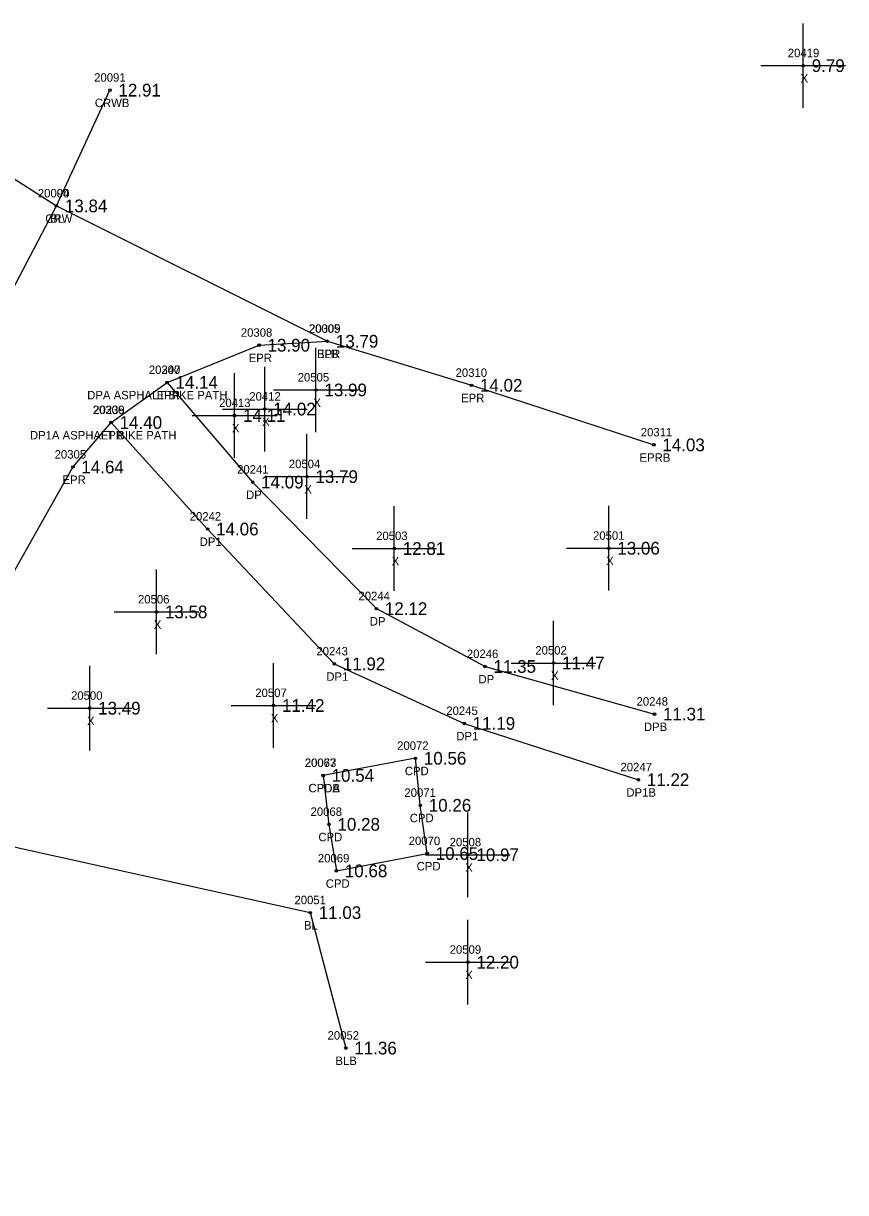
# Model space of a CAD drawing. Extents: x 2072302 to 2072980, y 127650 to 129736.
# Drawn here: x 2072882.9 to 2072980, y 128531.6 to 128669.8 of the extents above; entities that cross this region are included whole.
import ezdxf

# ---------------------------------------------------------------- set-up
doc = ezdxf.new("R2010")
doc.units = 0
for name, color, linetype in [('RD_DTM_BkLn1', 7, 'Continuous'), ('RD_DTM_BkLn_txCode', 7, 'Continuous'), ('RD_EX_Conc', 7, 'Continuous'), ('RD_EX_Conc_txCode', 7, 'Continuous'), ('RD_EX_Driveway', 7, 'Continuous'), ('RD_EX_Driveway_txCode', 7, 'Continuous'), ('RD_EX_Misc', 7, 'Continuous'), ('RD_EX_Misc_txCode', 7, 'Continuous'), ('RD_EX_Road', 7, 'Continuous'), ('RD_EX_Road_txCode', 7, 'Continuous'), ('RD_EX_TX_Conc_ELEV', 7, 'Continuous'), ('RD_EX_TX_Driveway_ELEV', 7, 'Continuous'), ('RD_EX_TX_Misc_ELEV', 7, 'Continuous'), ('RD_EX_TX_Road_ELEV', 7, 'Continuous'), ('RD_HC_Survey_ELEV', 7, 'Continuous'), ('RD_HC_Survey_txCode', 7, 'Continuous'), ('RD_SMD_Locator', 7, 'Continuous')]:
    doc.layers.add(name, color=color, linetype=linetype)

msp = doc.modelspace()

# ---------------------------------------------------------------- linework, layer by layer
at = {"layer": 'RD_DTM_BkLn1'}
for points in [[(2072853.07, 128669.78), (2072886.77, 128648.23), (2072918.79, 128632.23)], [(2072783.68, 128341.98), (2072775.38, 128381.91), (2072773.13, 128410.46), (2072778.13, 128436.13), (2072789.72, 128460.89), (2072826.62, 128532.44), (2072863.13, 128603.15), (2072886.77, 128648.23), (2072893.1, 128661.91)], [(2072791.29, 128345.62), (2072800.72, 128429.53), (2072808.9, 128452.58), (2072870.32, 128568.64), (2072876.57, 128573.6), (2072916.77, 128564.68), (2072920.97, 128548.67)]]:
    msp.add_lwpolyline(points, dxfattribs=at)
at = {"layer": 'RD_EX_Conc'}
msp.add_lwpolyline([(2072918.29, 128580.9), (2072918.98, 128575.12), (2072919.85, 128569.62), (2072930.59, 128571.67), (2072929.77, 128577.37), (2072929.19, 128582.93), (2072918.29, 128580.9)], dxfattribs=at)
at = {"layer": 'RD_EX_Driveway'}
for points in [[(2072899.84, 128627.36), (2072909.96, 128615.58), (2072924.58, 128600.62), (2072937.42, 128593.78), (2072957.44, 128588.15)], [(2072893.24, 128622.62), (2072904.64, 128610.03), (2072919.61, 128594.09), (2072934.96, 128587.05), (2072955.54, 128580.39)]]:
    msp.add_lwpolyline(points, dxfattribs=at)
at = {"layer": 'RD_EX_Misc'}
for p, q in [((2072975.02, 128659.81), (2072975.02, 128669.81)), ((2072970.02, 128664.81), (2072980.02, 128664.81)), ((2072917.44, 128621.47), (2072917.44, 128631.47)), ((2072911.39, 128619.21), (2072911.39, 128629.21)), ((2072907.82, 128618.45), (2072907.82, 128628.45)), ((2072912.44, 128626.47), (2072922.44, 128626.47)), ((2072906.39, 128624.21), (2072916.39, 128624.21)), ((2072902.82, 128623.45), (2072912.82, 128623.45)), ((2072916.38, 128611.23), (2072916.38, 128621.23)), ((2072911.38, 128616.23), (2072921.38, 128616.23)), ((2072926.7, 128602.73), (2072926.7, 128612.73)), ((2072952.05, 128602.76), (2072952.05, 128612.76)), ((2072921.7, 128607.73), (2072931.7, 128607.73)), ((2072947.05, 128607.76), (2072957.05, 128607.76)), ((2072898.59, 128595.23), (2072898.59, 128605.23)), ((2072893.59, 128600.23), (2072903.59, 128600.23)), ((2072945.52, 128589.19), (2072945.52, 128599.19)), ((2072890.7, 128583.85), (2072890.7, 128593.85)), ((2072912.43, 128584.17), (2072912.43, 128594.17)), ((2072940.52, 128594.19), (2072950.52, 128594.19)), ((2072907.43, 128589.17), (2072917.43, 128589.17)), ((2072885.7, 128588.85), (2072895.7, 128588.85)), ((2072935.4, 128566.52), (2072935.4, 128576.52)), ((2072930.4, 128571.52), (2072940.4, 128571.52)), ((2072935.4, 128553.82), (2072935.4, 128563.82)), ((2072930.4, 128558.82), (2072940.4, 128558.82))]:
    msp.add_line(p, q, dxfattribs=at)
at = {"layer": 'RD_EX_Road'}
msp.add_lwpolyline([(2072789.45, 128345.69), (2072789.46, 128382.93), (2072788.01, 128408.09), (2072794.06, 128431.26), (2072804.3, 128453.88), (2072840.7, 128525.64), (2072876.68, 128596.08), (2072888.72, 128617.36), (2072893.24, 128622.62), (2072899.84, 128627.36), (2072910.72, 128631.76), (2072918.79, 128632.23), (2072935.82, 128627.02), (2072957.37, 128619.98)], dxfattribs=at)
at = {"layer": 'RD_SMD_Locator'}
for centre in [(2072975.02, 128664.81), (2072893.1, 128661.91), (2072886.77, 128648.23), (2072886.77, 128648.23), (2072910.72, 128631.76), (2072918.79, 128632.23), (2072918.79, 128632.23), (2072899.84, 128627.36), (2072899.84, 128627.36), (2072917.44, 128626.47), (2072935.82, 128627.02), (2072907.82, 128623.45), (2072911.39, 128624.21), (2072893.24, 128622.62), (2072893.24, 128622.62), (2072957.37, 128619.98), (2072888.72, 128617.36), (2072909.96, 128615.58), (2072916.38, 128616.23), (2072904.64, 128610.03), (2072926.7, 128607.73), (2072952.05, 128607.76), (2072898.59, 128600.23), (2072924.58, 128600.62), (2072919.61, 128594.09), (2072937.42, 128593.78), (2072945.52, 128594.19), (2072912.43, 128589.17), (2072890.7, 128588.85), (2072957.44, 128588.15), (2072934.96, 128587.05), (2072929.19, 128582.93), (2072918.29, 128580.9), (2072918.29, 128580.9), (2072955.54, 128580.39), (2072929.77, 128577.37), (2072918.98, 128575.12), (2072930.59, 128571.67), (2072935.4, 128571.52), (2072919.85, 128569.62), (2072916.77, 128564.68), (2072935.4, 128558.82), (2072920.97, 128548.67)]:
    msp.add_circle(centre, 0.15, dxfattribs=at)

# ---------------------------------------------------------------- texts
at = {"layer": 'RD_DTM_BkLn_txCode'}
for s, p in [('20004', (2072884.58, 128649.23)), ('BL', (2072886.02, 128646.23)), ('20005', (2072916.59, 128633.23)), ('BLB', (2072917.56, 128630.23)), ('20051', (2072914.9, 128565.68)), ('BL', (2072916.02, 128562.68)), ('20052', (2072918.81, 128549.67)), ('BLB', (2072919.74, 128546.67))]:
    msp.add_text(s, height=1, dxfattribs=at).set_placement(p)
at = {"layer": 'RD_EX_Conc_txCode'}
for s, p in [('20072', (2072927.03, 128583.93)), ('20067', (2072916.11, 128581.9)), ('20073', (2072916.13, 128581.9)), ('CPD', (2072927.94, 128580.93)), ('CPDA', (2072916.55, 128578.9)), ('CPDB', (2072916.57, 128578.9)), ('20071', (2072927.89, 128578.37)), ('20068', (2072916.8, 128576.12)), ('CPD', (2072928.52, 128575.37)), ('CPD', (2072917.73, 128573.12)), ('20070', (2072928.4, 128572.67)), ('20069', (2072917.67, 128570.62)), ('CPD', (2072929.34, 128569.67)), ('CPD', (2072918.6, 128567.62))]:
    msp.add_text(s, height=1, dxfattribs=at).set_placement(p)
at = {"layer": 'RD_EX_Driveway_txCode'}
for s, p in [('20240', (2072897.69, 128628.36)), ('DPA ASPHALT BIKE PATH', (2072890.41, 128625.36)), ('20239', (2072891.12, 128623.62)), ('DP1A ASPHALT BIKE PATH', (2072883.64, 128620.62)), ('20241', (2072908.12, 128616.58)), ('DP', (2072909.18, 128613.58)), ('20242', (2072902.52, 128611.03)), ('DP1', (2072903.7, 128608.03)), ('20244', (2072922.46, 128601.62)), ('DP', (2072923.8, 128598.62)), ('20243', (2072917.49, 128595.09)), ('20246', (2072935.27, 128594.78)), ('DP1', (2072918.66, 128592.09)), ('DP', (2072936.64, 128591.78)), ('20245', (2072932.84, 128588.05)), ('20248', (2072955.32, 128589.15)), ('DPB', (2072956.19, 128586.15)), ('DP1', (2072934.02, 128585.05)), ('20247', (2072953.42, 128581.39)), ('DP1B', (2072954.12, 128578.39))]:
    msp.add_text(s, height=1, dxfattribs=at).set_placement(p)
at = {"layer": 'RD_EX_Misc_txCode'}
for s, p in [('20419', (2072973.19, 128665.81)), ('X', (2072974.71, 128662.81)), ('20505', (2072915.28, 128627.47)), ('20413', (2072905.99, 128624.45)), ('20412', (2072909.56, 128625.21)), ('X', (2072917.13, 128624.47)), ('X', (2072907.51, 128621.45)), ('X', (2072911.08, 128622.21)), ('20504', (2072914.23, 128617.23)), ('X', (2072916.07, 128614.23)), ('20501', (2072950.18, 128608.76)), ('20503', (2072924.55, 128608.73)), ('X', (2072926.39, 128605.73)), ('X', (2072951.74, 128605.76)), ('20506', (2072896.41, 128601.23)), ('X', (2072898.28, 128598.23)), ('20502', (2072943.36, 128595.19)), ('X', (2072945.21, 128592.19)), ('20500', (2072888.5, 128589.85)), ('20507', (2072910.27, 128590.17)), ('X', (2072890.39, 128586.85)), ('X', (2072912.11, 128587.17)), ('20508', (2072933.24, 128572.52)), ('X', (2072935.08, 128569.52)), ('20509', (2072933.24, 128559.82)), ('X', (2072935.08, 128556.82))]:
    msp.add_text(s, height=1, dxfattribs=at).set_placement(p)
at = {"layer": 'RD_EX_Road_txCode'}
for s, p in [('20308', (2072908.56, 128632.76)), ('20309', (2072916.63, 128633.23)), ('EPR', (2072909.49, 128629.76)), ('EPR', (2072917.56, 128630.23)), ('20307', (2072897.69, 128628.36)), ('20310', (2072933.94, 128628.02)), ('EPR', (2072898.61, 128625.36)), ('EPR', (2072934.59, 128625.02)), ('20306', (2072891.06, 128623.62)), ('EPR', (2072892.01, 128620.62)), ('20311', (2072955.82, 128620.98)), ('20305', (2072886.56, 128618.36)), ('EPRB', (2072955.67, 128617.98)), ('EPR', (2072887.49, 128615.36))]:
    msp.add_text(s, height=1, dxfattribs=at).set_placement(p)
at = {"layer": 'RD_EX_TX_Conc_ELEV'}
for s, p in [('10.56', (2072930.19, 128582.18)), ('10.54', (2072919.29, 128580.15)), ('10.54', (2072919.29, 128580.15)), ('10.26', (2072930.77, 128576.62)), ('10.28', (2072919.98, 128574.37)), ('10.65', (2072931.59, 128570.92)), ('10.68', (2072920.85, 128568.87))]:
    msp.add_text(s, height=1.5, dxfattribs=at).set_placement(p)
at = {"layer": 'RD_EX_TX_Driveway_ELEV'}
for s, p in [('14.14', (2072900.84, 128626.61)), ('14.40', (2072894.24, 128621.87)), ('14.09', (2072910.96, 128614.83)), ('14.06', (2072905.64, 128609.28)), ('12.12', (2072925.58, 128599.87)), ('11.92', (2072920.61, 128593.34)), ('11.35', (2072938.42, 128593.03)), ('11.19', (2072935.96, 128586.3)), ('11.31', (2072958.44, 128587.4)), ('11.22', (2072956.54, 128579.64))]:
    msp.add_text(s, height=1.5, dxfattribs=at).set_placement(p)
at = {"layer": 'RD_EX_TX_Misc_ELEV'}
for s, p in [('9.79', (2072976.02, 128664.06)), ('13.84', (2072887.77, 128647.48)), ('13.79', (2072919.79, 128631.48)), ('13.99', (2072918.44, 128625.72)), ('14.02', (2072912.39, 128623.46)), ('14.11', (2072908.82, 128622.7)), ('13.79', (2072917.38, 128615.48)), ('12.81', (2072927.7, 128606.98)), ('13.06', (2072953.05, 128607.01)), ('13.58', (2072899.59, 128599.48)), ('11.47', (2072946.52, 128593.44)), ('13.49', (2072891.7, 128588.1)), ('11.42', (2072913.43, 128588.42)), ('10.97', (2072936.4, 128570.77)), ('11.03', (2072917.77, 128563.93)), ('12.20', (2072936.4, 128558.07)), ('11.36', (2072921.97, 128547.92))]:
    msp.add_text(s, height=1.5, dxfattribs=at).set_placement(p)
at = {"layer": 'RD_EX_TX_Road_ELEV'}
for s, p in [('13.90', (2072911.72, 128631.01)), ('13.79', (2072919.79, 128631.48)), ('14.14', (2072900.84, 128626.61)), ('14.02', (2072936.82, 128626.27)), ('14.40', (2072894.24, 128621.87)), ('14.03', (2072958.37, 128619.23)), ('14.64', (2072889.72, 128616.61))]:
    msp.add_text(s, height=1.5, dxfattribs=at).set_placement(p)
at = {"layer": 'RD_HC_Survey_ELEV'}
for s, p in [('12.91', (2072894.1, 128661.16)), ('13.84', (2072887.77, 128647.48))]:
    msp.add_text(s, height=1.5, dxfattribs=at).set_placement(p)
at = {"layer": 'RD_HC_Survey_txCode'}
for s, p in [('20091', (2072891.23, 128662.91)), ('CRWB', (2072891.31, 128659.91)), ('20090', (2072884.58, 128649.23)), ('CRW', (2072885.46, 128646.23))]:
    msp.add_text(s, height=1, dxfattribs=at).set_placement(p)

doc.saveas('drawing.dxf')
